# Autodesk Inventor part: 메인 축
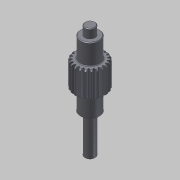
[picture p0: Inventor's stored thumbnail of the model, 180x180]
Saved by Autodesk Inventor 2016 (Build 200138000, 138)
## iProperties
Created: 2016-02
Part Number: 메인 축
Material: 강철, 연강
Document SubType Name: Modeling
Categories: <?xml version="1.0" encoding="UTF-16"?> <MemberInstance><Categories><FamilyTemplate><FamilyTemplateParameter ValueType="xs:double" Id="1" ObjectReferenceKey="da
Density: 7.86 g/cm^3
Appearance: 강철
CustomPartVersion: 1
Author: mdu
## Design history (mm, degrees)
sketch "Sketch1"
  geometry: C1 r 12 at (0, 0)
  constraints: 1 centre point
  dimensions: "d0" = 24 diameter of C1 (= da_da)
extrude "Extrusion1" new body sketch "Sketch1" distance "d1" = 20 (= da_b); taper "d2" = 0 deg
workplane "Work Plane2"
feature "피치 지름" dims "d4" = 10, "d5" = 0
workplane "Work Plane8"
workplane "Work Plane9"
chamfer "모따기1" distance "d49" = 1; stored, may be unused: second distance "d50" = 2, angle "d51" = 45 deg
sketch "스케치3"
  geometry: C1 r 7.5 at (0, 0); 1 further point
  constraints: 1 centre point, 1 coincident
  dimensions: "d52" = 15 diameter of C1
extrude "돌출2" join sketch "스케치3" distance "d53" = 16; taper "d54" = 0 deg
sketch "스케치4"
  geometry: C1 r 4 at (0, 0); 1 further point
  constraints: 1 centre point, 1 coincident
  dimensions: "d55" = 8 diameter of C1
extrude "돌출3" join sketch "스케치4" distance "d56" = 7; taper "d57" = 0 deg
sketch "스케치5"
  geometry: C1 r 7.5 at (0, 0) reference; C2 r 7.5 at (0, 0) reference; 1 further point
extrude "돌출4" join sketch "스케치5" distance "d62" = 16; taper "d63" = 0 deg
sketch "스케치6"
  geometry: C1 r 4 at (0, 0); 1 further point
  constraints: 1 centre point, 1 coincident
  dimensions: "d64" = 8 diameter of C1
extrude "돌출5" join sketch "스케치6" distance "d65" = 30; taper "d66" = 0 deg
chamfer "모따기2" distance "d58" = 0.5; stored, may be unused: second distance "d59" = 2, angle "d60" = 45 deg
fillet "모깎기1" dims "d61" = 0.5
feature "스퍼 기어" dims "d34" = 1.428 (computed from da_z), "da_b" = 20, "da_d" = 22, "da_aw" = 31, "da_da" = 24, "da_df" = 19.5, "da_dw" = 22, angle "da_beta" = 0 deg, "da_lefttooth" = 0, "da_righttooth" = 0
body "Solid1"
sketch "Sketch2"
  geometry: C1 r 12 at (0, 0) reference; C2 r 11 at (0, 0)
  constraints: 1 centre point, 1 coincident
  dimensions: "d3" = 22 diameter of C2 (= da_dw)
body "Srf1"
node "투영된 루프1"
other parameters: "d16" = 31 (= da_aw), "d17" = 0, "d39" = 0, "d41" = 0, "d43" = 31 (= da_aw), "d46" = 31 (= da_aw), "d47" = 0, "d48" = 0
